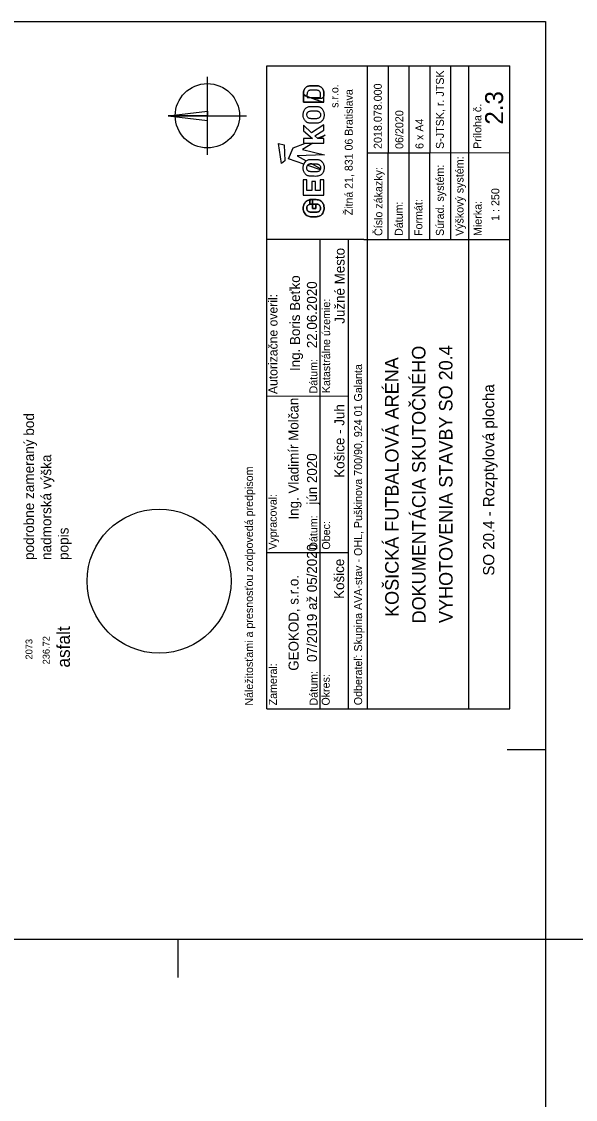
# Model space of a CAD drawing. Extents: x -264205 to -263659, y -1242401 to -1241986.
# Drawn here: x -263940.1 to -263903.9, y -1242055.9 to -1241985.5 of the extents above; entities that cross this region are included whole.
import ezdxf

# ---------------------------------------------------------------- set-up
doc = ezdxf.new("R2010")
doc.units = 0
for name, color, linetype in [('LEGENDA_2-3', 7, 'Continuous'), ('RAM_NA_TLAC_2-2_1-250', 7, 'Continuous'), ('RAM_NA_TLAC_2-3_1-250', 7, 'Continuous'), ('ROZPISKA_2-3', 7, 'Continuous')]:
    doc.layers.add(name, color=color, linetype=linetype)

msp = doc.modelspace()

# ---------------------------------------------------------------- linework, layer by layer
at = {"layer": 'RAM_NA_TLAC_2-2_1-250'}
msp.add_line((-263929.895, -1242045.402), (-263929.895, -1242047.902), dxfattribs=at)
msp.add_lwpolyline([(-263982.395, -1242045.402), (-263692.395, -1242045.402), (-263692.395, -1242119.652), (-263982.395, -1242119.652)], close=True, dxfattribs=at)
at = {"layer": 'RAM_NA_TLAC_2-3_1-250'}
msp.add_line((-263908.389, -1242033.011), (-263905.889, -1242033.011), dxfattribs=at)
msp.add_lwpolyline([(-263980.139, -1242275.511), (-263980.139, -1241985.511), (-263905.889, -1241985.511), (-263905.889, -1242275.511)], close=True, dxfattribs=at)
at = {"layer": 'ROZPISKA_2-3'}
for p, q in [((-263924.1, -1241988.398), (-263908.218, -1241988.397)), ((-263924.1, -1242030.368), (-263924.1, -1241988.398)), ((-263917.522, -1241999.737), (-263917.521, -1241988.396)), ((-263916.159, -1241999.74), (-263916.157, -1241988.398)), ((-263914.798, -1241999.743), (-263914.799, -1241988.396)), ((-263913.437, -1241999.742), (-263913.435, -1241988.395)), ((-263912.075, -1241999.74), (-263912.076, -1241988.396)), ((-263910.896, -1242030.369), (-263910.897, -1241988.396)), ((-263908.218, -1242030.369), (-263908.218, -1241988.397)), ((-263927.975, -1241994.209), (-263927.975, -1241989.109)), ((-263921.701, -1241990.767), (-263921.701, -1241990.339)), ((-263921.701, -1241990.339), (-263921.701, -1241990.767)), ((-263920.361, -1241990.768), (-263921.701, -1241990.767)), ((-263921.701, -1241990.767), (-263920.361, -1241990.768)), ((-263921.468, -1241990.474), (-263920.594, -1241990.474)), ((-263921.468, -1241990.474), (-263920.594, -1241990.474)), ((-263930.525, -1241991.659), (-263927.975, -1241991.357)), ((-263930.525, -1241991.659), (-263925.425, -1241991.659)), ((-263930.525, -1241991.659), (-263927.975, -1241991.961)), ((-263921.165, -1241992.771), (-263921.705, -1241992.277)), ((-263921.705, -1241992.277), (-263921.705, -1241992.634)), ((-263920.361, -1241992.25), (-263921.165, -1241992.771)), ((-263920.361, -1241992.589), (-263920.361, -1241992.25)), ((-263921.705, -1241992.634), (-263921.118, -1241993.152)), ((-263920.787, -1241993.129), (-263920.275, -1241992.928)), ((-263920.275, -1241992.928), (-263920.637, -1241993.152)), ((-263922.671, -1241994.479), (-263922.361, -1241993.747)), ((-263922.361, -1241993.747), (-263921.575, -1241993.438)), ((-263921.098, -1241993.438), (-263921.767, -1241993.855)), ((-263921.118, -1241993.152), (-263921.705, -1241993.152)), ((-263921.705, -1241993.152), (-263921.705, -1241993.438)), ((-263921.575, -1241993.438), (-263921.098, -1241993.438)), ((-263920.327, -1241994.205), (-263922.105, -1241994.27)), ((-263922.105, -1241994.27), (-263921.517, -1241994.598)), ((-263921.767, -1241993.855), (-263920.327, -1241994.205)), ((-263917.52, -1241994.069), (-263913.435, -1241994.068)), ((-263913.435, -1241994.068), (-263908.219, -1241994.067)), ((-263921.674, -1241994.808), (-263922.671, -1241994.479)), ((-263921.722, -1241995.075), (-263921.723, -1241995.052)), ((-263921.482, -1241995.07), (-263921.483, -1241995.055)), ((-263921.482, -1241995.07), (-263921.483, -1241995.055)), ((-263921.428, -1241994.889), (-263920.6, -1241995.163)), ((-263921.289, -1241997.132), (-263921.289, -1241997.43)), ((-263921.289, -1241997.43), (-263921.289, -1241997.132)), ((-263917.748, -1241999.74), (-263924.101, -1241999.741)), ((-263920.615, -1242030.37), (-263920.614, -1241999.74)), ((-263918.768, -1242030.368), (-263918.769, -1241999.741)), ((-263917.748, -1241999.74), (-263913.662, -1241999.74)), ((-263917.518, -1242030.371), (-263917.522, -1241999.737)), ((-263913.662, -1241999.74), (-263908.22, -1241999.741)), ((-263924.098, -1242009.951), (-263918.768, -1242009.948)), ((-263924.101, -1242020.161), (-263918.766, -1242020.157)), ((-263924.1, -1242030.368), (-263908.218, -1242030.369))]:
    msp.add_line(p, q, dxfattribs=at)
for points in [[(-263930.525, -1241991.659), (-263927.975, -1241991.357), (-263927.975, -1241991.659)], [(-263923.134, -1241994.77), (-263923.321, -1241993.47), (-263922.95, -1241993.561), (-263922.916, -1241994.597)], [(-263921.711, -1241996.837), (-263920.361, -1241996.837), (-263920.361, -1241995.848), (-263920.599, -1241995.848), (-263920.599, -1241996.54), (-263920.922, -1241996.54), (-263920.922, -1241995.948), (-263921.157, -1241995.948), (-263921.157, -1241996.54), (-263921.472, -1241996.54), (-263921.472, -1241995.848), (-263921.711, -1241995.848)]]:
    msp.add_lwpolyline(points, close=True, dxfattribs=at)
for points in [[(-263921.705, -1241993.438), (-263920.361, -1241993.438), (-263920.361, -1241993.152), (-263920.763, -1241993.152), (-263920.964, -1241992.961), (-263920.361, -1241992.589)], [(-263920.637, -1241993.152), (-263920.763, -1241993.152), (-263920.787, -1241993.129)], [(-263921.517, -1241994.598), (-263921.53, -1241994.607), (-263921.549, -1241994.624), (-263921.566, -1241994.641), (-263921.583, -1241994.661), (-263921.599, -1241994.68), (-263921.615, -1241994.703), (-263921.627, -1241994.721), (-263921.64, -1241994.741), (-263921.654, -1241994.765), (-263921.665, -1241994.786), (-263921.674, -1241994.808)], [(-263921.154, -1241994.8), (-263921.183, -1241994.801), (-263921.22, -1241994.802), (-263921.254, -1241994.805), (-263921.287, -1241994.81), (-263921.317, -1241994.818), (-263921.35, -1241994.83), (-263921.382, -1241994.848), (-263921.407, -1241994.868), (-263921.428, -1241994.889)], [(-263920.588, -1241995.116), (-263921.154, -1241994.8)], [(-263920.6, -1241995.163), (-263920.597, -1241995.155), (-263920.594, -1241995.146), (-263920.592, -1241995.139), (-263920.59, -1241995.13), (-263920.589, -1241995.122), (-263920.588, -1241995.116)], [(-263920.891, -1241997.42), (-263920.891, -1241997.701), (-263921.114, -1241997.701), (-263921.114, -1241997.129)], [(-263921.114, -1241997.129), (-263921.114, -1241997.701), (-263920.891, -1241997.701), (-263920.891, -1241997.42)]]:
    msp.add_lwpolyline(points, dxfattribs=at)
for centre, radius in [((-263927.975, -1241991.659), 2.1), ((-263931.128, -1242022.03), 4.702)]:
    msp.add_circle(centre, radius, dxfattribs=at)
for points in [[(-263921.701, -1241990.339), (-263921.701, -1241990.198), (-263921.696, -1241990.112), (-263921.684, -1241990.047), (-263921.655, -1241989.964), (-263921.61, -1241989.885), (-263921.536, -1241989.804), (-263921.451, -1241989.746), (-263921.372, -1241989.717), (-263921.248, -1241989.698), (-263921.187, -1241989.697), (-263920.92, -1241989.697), (-263920.832, -1241989.7), (-263920.761, -1241989.707), (-263920.685, -1241989.719), (-263920.591, -1241989.757), (-263920.505, -1241989.824), (-263920.427, -1241989.923), (-263920.391, -1241990.004), (-263920.368, -1241990.086), (-263920.361, -1241990.155), (-263920.361, -1241990.179), (-263920.361, -1241990.768), (-263921.701, -1241990.339), (-263920.361, -1241990.768)], [(-263920.361, -1241990.768), (-263920.361, -1241990.179), (-263920.361, -1241990.155), (-263920.368, -1241990.086), (-263920.391, -1241990.004), (-263920.427, -1241989.923), (-263920.505, -1241989.824), (-263920.591, -1241989.757), (-263920.685, -1241989.719), (-263920.761, -1241989.707), (-263920.832, -1241989.7), (-263920.92, -1241989.697), (-263921.187, -1241989.697), (-263921.248, -1241989.698), (-263921.372, -1241989.717), (-263921.451, -1241989.746), (-263921.536, -1241989.804), (-263921.61, -1241989.885), (-263921.655, -1241989.964), (-263921.684, -1241990.047), (-263921.696, -1241990.112), (-263921.701, -1241990.198), (-263921.701, -1241990.339), (-263920.361, -1241990.768), (-263921.701, -1241990.339)], [(-263920.594, -1241990.474), (-263920.593, -1241990.388), (-263920.593, -1241990.299), (-263920.594, -1241990.205), (-263920.593, -1241990.189), (-263920.601, -1241990.154), (-263920.628, -1241990.101), (-263920.675, -1241990.032), (-263920.759, -1241989.999), (-263920.849, -1241989.989), (-263920.975, -1241989.991), (-263921.119, -1241989.989), (-263921.236, -1241989.991), (-263921.315, -1241989.997), (-263921.37, -1241990.028), (-263921.426, -1241990.088), (-263921.456, -1241990.155), (-263921.469, -1241990.246), (-263921.469, -1241990.308), (-263921.468, -1241990.435), (-263921.468, -1241990.474)], [(-263920.594, -1241990.474), (-263920.593, -1241990.388), (-263920.593, -1241990.299), (-263920.594, -1241990.205), (-263920.593, -1241990.189), (-263920.601, -1241990.154), (-263920.628, -1241990.101), (-263920.675, -1241990.032), (-263920.759, -1241989.999), (-263920.849, -1241989.989), (-263920.975, -1241989.991), (-263921.119, -1241989.989), (-263921.236, -1241989.991), (-263921.315, -1241989.997), (-263921.37, -1241990.028), (-263921.426, -1241990.088), (-263921.456, -1241990.155), (-263921.469, -1241990.246), (-263921.469, -1241990.308), (-263921.468, -1241990.435), (-263921.468, -1241990.474)], [(-263921.723, -1241991.592), (-263921.716, -1241991.691), (-263921.693, -1241991.797), (-263921.656, -1241991.884), (-263921.615, -1241991.956), (-263921.56, -1241992.018), (-263921.497, -1241992.071), (-263921.417, -1241992.115), (-263921.329, -1241992.138), (-263921.244, -1241992.149), (-263921.149, -1241992.149), (-263920.859, -1241992.152), (-263920.751, -1241992.141), (-263920.631, -1241992.101), (-263920.546, -1241992.051), (-263920.49, -1241991.998), (-263920.437, -1241991.922), (-263920.398, -1241991.853), (-263920.368, -1241991.779), (-263920.354, -1241991.689), (-263920.35, -1241991.592), (-263920.359, -1241991.477), (-263920.387, -1241991.376), (-263920.421, -1241991.295), (-263920.476, -1241991.214), (-263920.534, -1241991.152), (-263920.605, -1241991.104), (-263920.698, -1241991.064), (-263920.792, -1241991.048), (-263920.91, -1241991.044), (-263921.188, -1241991.046), (-263921.297, -1241991.051), (-263921.394, -1241991.074), (-263921.493, -1241991.12), (-263921.566, -1241991.182), (-263921.638, -1241991.279), (-263921.682, -1241991.366), (-263921.707, -1241991.47), (-263921.723, -1241991.571), (-263921.723, -1241991.592), (-263921.723, -1241991.592), (-263921.723, -1241991.592)], [(-263921.483, -1241991.595), (-263921.476, -1241991.667), (-263921.446, -1241991.738), (-263921.4, -1241991.794), (-263921.347, -1241991.828), (-263921.274, -1241991.847), (-263921.193, -1241991.851), (-263921.071, -1241991.854), (-263920.933, -1241991.854), (-263920.838, -1241991.854), (-263920.753, -1241991.84), (-263920.679, -1241991.803), (-263920.631, -1241991.754), (-263920.601, -1241991.704), (-263920.587, -1241991.646), (-263920.587, -1241991.6), (-263920.587, -1241991.554), (-263920.605, -1241991.48), (-263920.654, -1241991.409), (-263920.707, -1241991.372), (-263920.774, -1241991.351), (-263920.85, -1241991.34), (-263920.937, -1241991.34), (-263921.046, -1241991.339), (-263921.145, -1241991.34), (-263921.223, -1241991.34), (-263921.32, -1241991.358), (-263921.384, -1241991.388), (-263921.437, -1241991.441), (-263921.469, -1241991.503), (-263921.481, -1241991.556), (-263921.483, -1241991.595), (-263921.483, -1241991.595), (-263921.483, -1241991.595)], [(-263921.723, -1241995.052), (-263921.723, -1241995.045), (-263921.724, -1241995.004), (-263921.706, -1241994.929), (-263921.688, -1241994.828), (-263921.636, -1241994.732), (-263921.575, -1241994.645), (-263921.492, -1241994.573), (-263921.398, -1241994.532), (-263921.294, -1241994.506), (-263921.131, -1241994.507), (-263920.963, -1241994.502), (-263920.799, -1241994.506), (-263920.695, -1241994.521), (-263920.608, -1241994.56), (-263920.532, -1241994.609), (-263920.473, -1241994.677), (-263920.419, -1241994.751), (-263920.383, -1241994.841), (-263920.354, -1241994.94), (-263920.347, -1241995.047), (-263920.354, -1241995.147), (-263920.362, -1241995.237), (-263920.397, -1241995.314), (-263920.439, -1241995.386), (-263920.484, -1241995.456), (-263920.549, -1241995.519), (-263920.637, -1241995.569), (-263920.744, -1241995.604), (-263920.92, -1241995.62), (-263921.084, -1241995.604), (-263921.241, -1241995.613), (-263921.331, -1241995.599), (-263921.418, -1241995.579), (-263921.497, -1241995.536), (-263921.561, -1241995.479), (-263921.618, -1241995.418), (-263921.659, -1241995.341), (-263921.698, -1241995.254), (-263921.717, -1241995.162), (-263921.721, -1241995.101), (-263921.722, -1241995.075)], [(-263921.483, -1241995.055), (-263921.483, -1241995.042), (-263921.482, -1241995.011), (-263921.47, -1241994.958), (-263921.439, -1241994.898), (-263921.388, -1241994.845), (-263921.312, -1241994.812), (-263921.23, -1241994.799), (-263921.138, -1241994.801), (-263921.043, -1241994.798), (-263920.944, -1241994.802), (-263920.853, -1241994.797), (-263920.776, -1241994.81), (-263920.707, -1241994.828), (-263920.645, -1241994.871), (-263920.603, -1241994.936), (-263920.584, -1241995.004), (-263920.588, -1241995.06), (-263920.584, -1241995.111), (-263920.598, -1241995.165), (-263920.631, -1241995.219), (-263920.68, -1241995.27), (-263920.753, -1241995.305), (-263920.841, -1241995.317), (-263920.947, -1241995.313), (-263921.065, -1241995.315), (-263921.179, -1241995.312), (-263921.272, -1241995.31), (-263921.345, -1241995.294), (-263921.405, -1241995.254), (-263921.45, -1241995.199), (-263921.479, -1241995.135), (-263921.482, -1241995.09), (-263921.482, -1241995.07)], [(-263921.483, -1241995.055), (-263921.483, -1241995.042), (-263921.482, -1241995.011), (-263921.47, -1241994.958), (-263921.439, -1241994.898), (-263921.388, -1241994.845), (-263921.312, -1241994.812), (-263921.23, -1241994.799), (-263921.138, -1241994.801), (-263921.043, -1241994.798), (-263920.944, -1241994.802), (-263920.853, -1241994.797), (-263920.776, -1241994.81), (-263920.707, -1241994.828), (-263920.645, -1241994.871), (-263920.603, -1241994.936), (-263920.584, -1241995.004), (-263920.588, -1241995.06), (-263920.584, -1241995.111), (-263920.598, -1241995.165), (-263920.631, -1241995.219), (-263920.68, -1241995.27), (-263920.753, -1241995.305), (-263920.841, -1241995.317), (-263920.947, -1241995.313), (-263921.065, -1241995.315), (-263921.179, -1241995.312), (-263921.272, -1241995.31), (-263921.345, -1241995.294), (-263921.405, -1241995.254), (-263921.45, -1241995.199), (-263921.479, -1241995.135), (-263921.482, -1241995.09), (-263921.482, -1241995.07)], [(-263921.114, -1241997.129), (-263920.944, -1241997.127), (-263920.791, -1241997.132), (-263920.655, -1241997.162), (-263920.546, -1241997.228), (-263920.454, -1241997.328), (-263920.393, -1241997.433), (-263920.358, -1241997.573), (-263920.349, -1241997.7), (-263920.358, -1241997.831), (-263920.401, -1241997.962), (-263920.476, -1241998.076), (-263920.563, -1241998.164), (-263920.681, -1241998.22), (-263920.812, -1241998.247), (-263920.9, -1241998.251), (-263921.167, -1241998.251), (-263921.311, -1241998.242), (-263921.433, -1241998.203), (-263921.538, -1241998.137), (-263921.643, -1241998.006), (-263921.704, -1241997.866), (-263921.722, -1241997.704), (-263921.709, -1241997.534), (-263921.634, -1241997.355), (-263921.503, -1241997.215), (-263921.289, -1241997.132), (-263921.114, -1241997.129), (-263921.289, -1241997.132)], [(-263921.289, -1241997.132), (-263921.503, -1241997.215), (-263921.634, -1241997.355), (-263921.709, -1241997.534), (-263921.722, -1241997.704), (-263921.704, -1241997.866), (-263921.643, -1241998.006), (-263921.538, -1241998.137), (-263921.433, -1241998.203), (-263921.311, -1241998.242), (-263921.167, -1241998.251), (-263920.9, -1241998.251), (-263920.812, -1241998.247), (-263920.681, -1241998.22), (-263920.563, -1241998.164), (-263920.476, -1241998.076), (-263920.401, -1241997.962), (-263920.358, -1241997.831), (-263920.349, -1241997.7), (-263920.358, -1241997.573), (-263920.393, -1241997.433), (-263920.454, -1241997.328), (-263920.546, -1241997.228), (-263920.655, -1241997.162), (-263920.791, -1241997.132), (-263920.944, -1241997.127), (-263921.114, -1241997.129), (-263921.289, -1241997.132), (-263921.114, -1241997.129)], [(-263921.289, -1241997.428), (-263921.363, -1241997.456), (-263921.435, -1241997.522), (-263921.476, -1241997.611), (-263921.483, -1241997.701), (-263921.472, -1241997.791), (-263921.43, -1241997.863), (-263921.374, -1241997.915), (-263921.312, -1241997.941), (-263921.221, -1241997.944), (-263921.12, -1241997.95), (-263921, -1241997.952), (-263920.858, -1241997.95), (-263920.753, -1241997.939), (-263920.67, -1241997.9), (-263920.622, -1241997.843), (-263920.593, -1241997.775), (-263920.585, -1241997.703), (-263920.589, -1241997.618), (-263920.626, -1241997.528), (-263920.687, -1241997.465), (-263920.757, -1241997.428), (-263920.838, -1241997.419), (-263920.891, -1241997.42), (-263921.289, -1241997.428), (-263920.891, -1241997.42)], [(-263920.891, -1241997.42), (-263920.838, -1241997.419), (-263920.757, -1241997.428), (-263920.687, -1241997.465), (-263920.626, -1241997.528), (-263920.589, -1241997.618), (-263920.585, -1241997.703), (-263920.593, -1241997.775), (-263920.622, -1241997.843), (-263920.67, -1241997.9), (-263920.753, -1241997.939), (-263920.858, -1241997.95), (-263921, -1241997.952), (-263921.12, -1241997.95), (-263921.221, -1241997.944), (-263921.312, -1241997.941), (-263921.374, -1241997.915), (-263921.43, -1241997.863), (-263921.472, -1241997.791), (-263921.483, -1241997.701), (-263921.476, -1241997.611), (-263921.435, -1241997.522), (-263921.363, -1241997.456), (-263921.289, -1241997.428), (-263920.891, -1241997.42), (-263921.289, -1241997.428)]]:
    msp.add_open_spline(points, degree=3, dxfattribs=at)

# ---------------------------------------------------------------- texts
at = {"layer": 'LEGENDA_2-3'}
for s, height, p in [('podrobne zameraný bod', 0.66129, (-263939.293, -1242020.65)), ('nadmorská výška', 0.66129, (-263938.168, -1242020.65)), ('popis', 0.6613, (-263937.043, -1242020.65)), ('asfalt', 0.8438, (-263936.952, -1242027.675)), ('2073', 0.45, (-263939.399, -1242027.144)), ('236.72', 0.45, (-263938.274, -1242027.461))]:
    msp.add_text(s, height=height, rotation=90, dxfattribs=at).set_placement(p)
at = {"layer": 'ROZPISKA_2-3'}
for s, height, rotation, p in [('S-JTSK, r. JTSK', 0.52245, 90, (-263912.527, -1241993.824)), ('s.r.o.', 0.5173, 90.00155, (-263919.416, -1241991.14)), ('Žitná 21, 831 06 Bratislava', 0.51728, 90.00155, (-263918.484, -1241998.155)), ('2018.078.000', 0.52245, 90, (-263916.584, -1241993.824)), ('2.3', 1.1755, 90, (-263908.66, -1241992.238)), ('Príloha č.', 0.5216, 90.00155, (-263910.08, -1241993.824)), ('06/2020', 0.5224, 90, (-263915.179, -1241993.824)), ('6 x A4', 0.5224, 90, (-263913.861, -1241993.824)), ('Výškový systém:', 0.52156, 90.00155, (-263911.248, -1241999.506)), ('Číslo zákazky:', 0.52157, 90.00155, (-263916.547, -1241999.506)), ('Súrad. systém:', 0.52157, 90.00155, (-263912.53, -1241999.506)), ('1 : 250', 0.5224, 90, (-263908.91, -1241998.521)), ('Formát:', 0.5217, 90.00155, (-263913.93, -1241999.506)), ('Dátum:', 0.5217, 90.00155, (-263915.212, -1241999.506)), ('Mierka:', 0.5217, 90.00155, (-263910.063, -1241999.506)), ('Južné Mesto', 0.65241, 90.04559, (-263919.01, -1242005.23)), ('Ing. Boris Beťko', 0.65241, 90.04559, (-263921.923, -1242008.317)), ('22.06.2020', 0.652, 90.04559, (-263920.819, -1242006.829)), ('Autorizačne overil:', 0.59461, 90.00155, (-263923.396, -1242009.827)), ('Katastrálne územie:', 0.5217, 90.00155, (-263919.957, -1242009.763)), ('DOKUMENTÁCIA SKUTOČNÉHO', 0.88076, 90.04559, (-263913.719, -1242024.789)), ('VYHOTOVENIA STAVBY SO 20.4', 0.88076, 90.04559, (-263911.957, -1242024.766)), ('Dátum:', 0.5217, 90.00155, (-263920.788, -1242009.782)), ('KOŠICKÁ FUTBALOVÁ ARÉNA', 0.88076, 90.04559, (-263915.481, -1242024.368)), ('Odberateľ: Skupina AVA-stav - OHL, Puškinova 700/90, 924 01 Galanta', 0.52157, 90.00155, (-263917.87, -1242030.129)), ('SO 20.4 - Rozptylová plocha', 0.73378, 90.04559, (-263909.235, -1242021.673)), ('Ing. Vladimír Molčan', 0.65209, 90.04559, (-263922.02, -1242018.01)), ('Košice - Juh', 0.65241, 90.04559, (-263919.023, -1242015.282)), ('jún 2020', 0.652, 90.04559, (-263920.816, -1242017.038)), ('Náležitosťami a presnosťou zodpovedá predpisom', 0.5217, 90.00155, (-263924.994, -1242030.158)), ('Vypracoval:', 0.5217, 90.00155, (-263923.447, -1242019.981)), ('Dátum:', 0.5217, 90.00155, (-263920.789, -1242019.986)), ('Obec:', 0.5217, 90.00155, (-263919.959, -1242019.972)), ('07/2019 až 05/2020', 0.65196, 90.04559, (-263920.816, -1242027.309)), ('Košice', 0.6523, 90.04559, (-263919.043, -1242023.188)), ('GEOKOD, s.r.o.', 0.65196, 90.04559, (-263922.018, -1242027.879)), ('Zameral:', 0.5217, 90.00155, (-263923.432, -1242030.142)), ('Dátum:', 0.5217, 90.00155, (-263920.775, -1242030.149)), ('Okres:', 0.5217, 90.00155, (-263919.984, -1242030.152))]:
    msp.add_text(s, height=height, rotation=rotation, dxfattribs=at).set_placement(p)

doc.saveas('drawing.dxf')
